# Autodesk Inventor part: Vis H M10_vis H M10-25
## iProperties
Shininess: 64.0
Length Units: 11269
Angle Units: 11279
Time Units: 11290
Mass Units: 11283
Length Display Precision: 3
Angle Display Precision: 2
Compacted: True
Part Number: Vis H M10_vis H M10-25
Document SubType Name: Modeling
Created: 2006-01
Material: Par défaut
Designer: riri
Density: 0.0
Volumn: 0.0
Area: 0.0
PropertySet Name: Model Information
Control State: 0
Master: False
Checked Out: False
Author: riri
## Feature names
1. Base1
